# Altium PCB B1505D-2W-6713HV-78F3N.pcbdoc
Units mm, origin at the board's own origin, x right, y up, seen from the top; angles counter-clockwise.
Board outline 50 x 30 mm, 2 copper layers (Top Layer, Bottom Layer), stack 0.78 mm thick; 21 components, 11 nets, 44 pads, 54 vias.
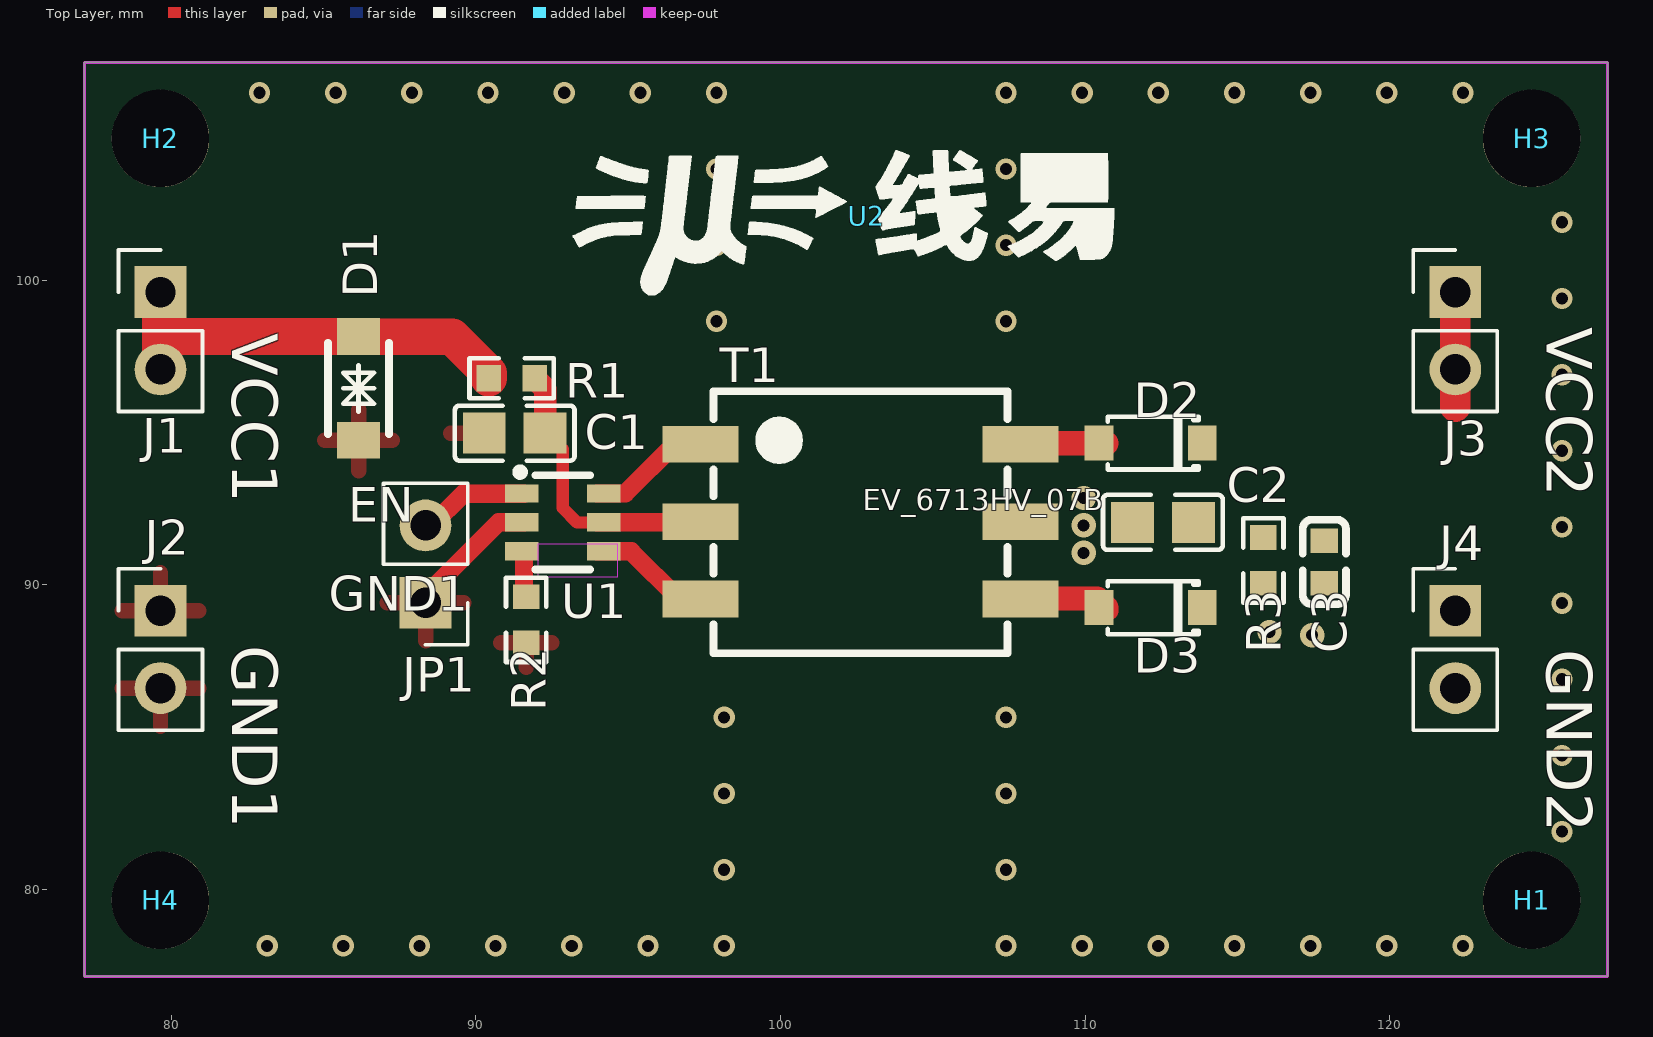
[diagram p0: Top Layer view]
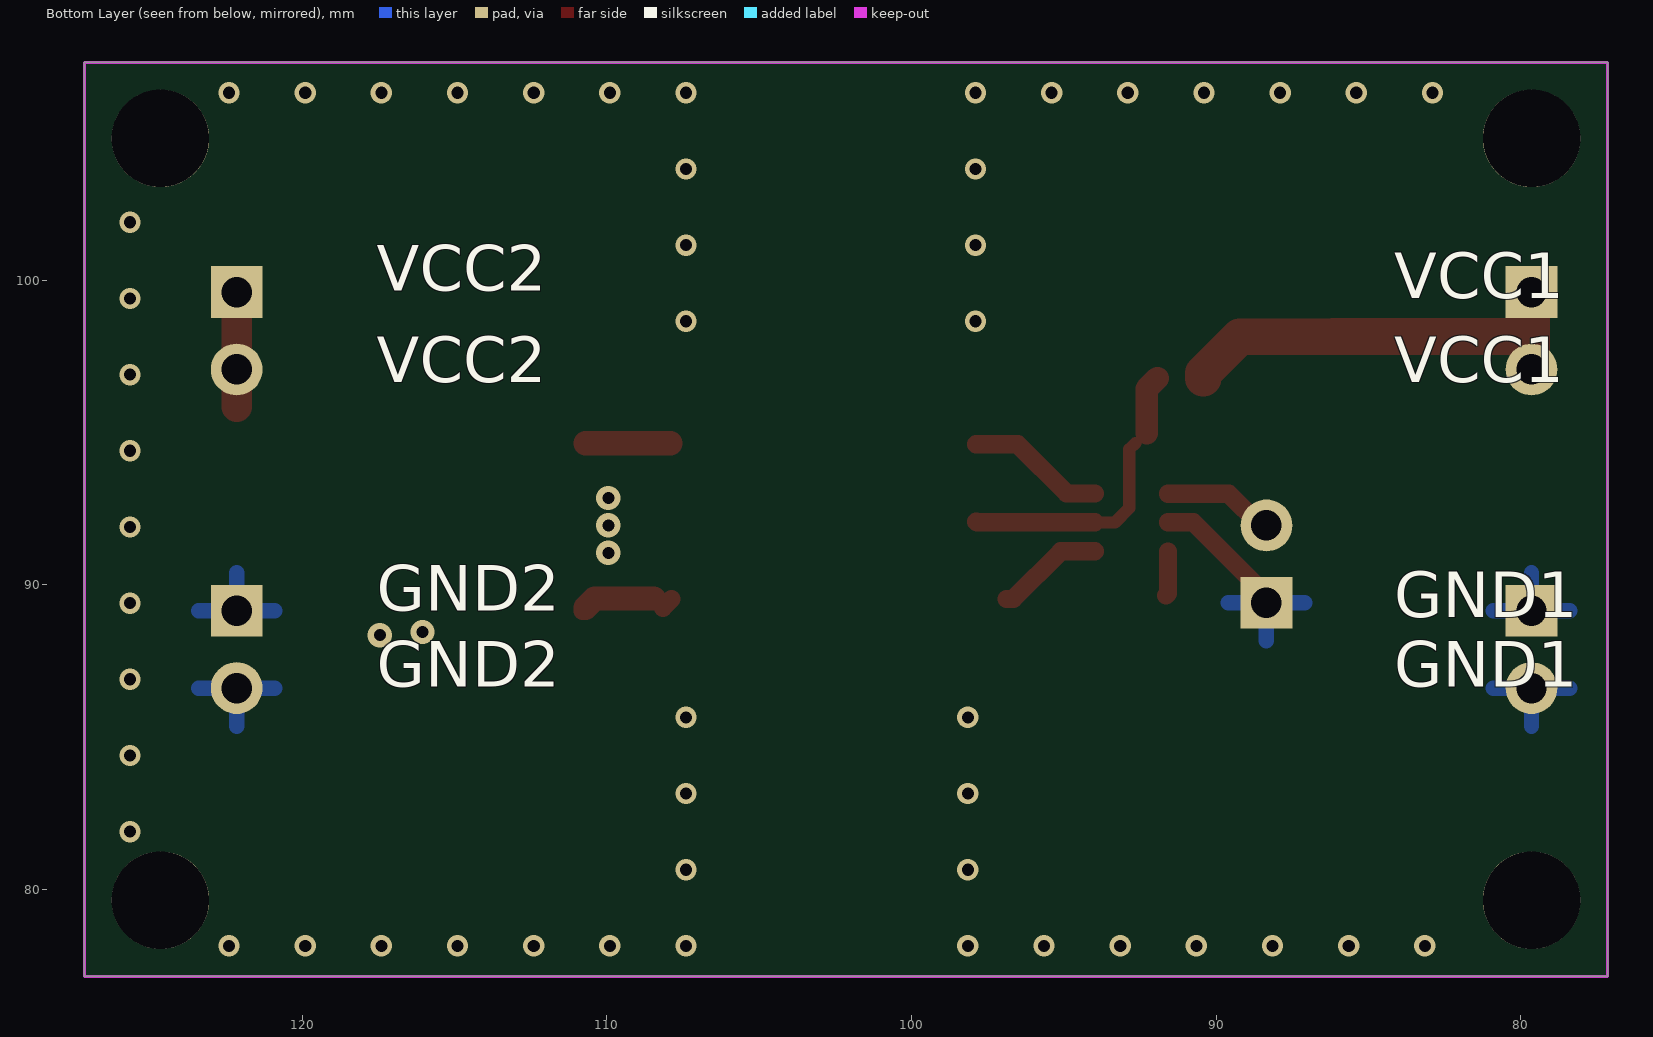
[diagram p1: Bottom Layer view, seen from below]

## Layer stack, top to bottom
Top Solder Mask Layer: solder mask 0.01, Dk 0
Top Layer: signal copper 0.035
Dielectric1: surface 0.71, FR4, Dk 4.5
Bottom Layer: signal copper 0.035
Bottom Solder Mask Layer: solder mask 0.01, Dk 0

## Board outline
77.15,107.15 127.15,107.15 127.15,77.15 77.15,77.15

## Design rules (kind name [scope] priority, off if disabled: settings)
BoardOutlineClearance safeClearance [All] p0: genericclearance=0.254 ignorepadtopadclearanceinfootprint=FALSE except(0: Arc-SplitContinuation Track-SplitContinuation SMDPad-SplitContinuation THPad-SplitContinuation Via-SplitContinuation Fill-SplitContinuation Poly-SplitContinuation Region-SplitContinuation Text-SplitContinuation)
BoardOutlineClearance Plane_innerPlane [All] p0: genericclearance=0.254 ignorepadtopadclearanceinfootprint=FALSE except(0: Arc-SplitContinuation Track-SplitContinuation SMDPad-SplitContinuation THPad-SplitContinuation Via-SplitContinuation Fill-SplitContinuation Poly-SplitContinuation Region-SplitContinuation Text-SplitContinuation)
BoardOutlineClearance Copper_CopperRegion [All] p0: genericclearance=0.254 ignorepadtopadclearanceinfootprint=FALSE except(0: Arc-SplitContinuation Track-SplitContinuation SMDPad-SplitContinuation THPad-SplitContinuation Via-SplitContinuation Fill-SplitContinuation Poly-SplitContinuation Region-SplitContinuation Text-SplitContinuation)
BoardOutlineClearance Copper_CopperRegion1 [All] p0: genericclearance=0.254 ignorepadtopadclearanceinfootprint=FALSE except(0: Arc-SplitContinuation Track-SplitContinuation SMDPad-SplitContinuation THPad-SplitContinuation Via-SplitContinuation Fill-SplitContinuation Poly-SplitContinuation Region-SplitContinuation Text-SplitContinuation)
BoardOutlineClearance Copper_CopperRegion2 [All] p0: genericclearance=0.254 ignorepadtopadclearanceinfootprint=FALSE except(0: Arc-SplitContinuation Track-SplitContinuation SMDPad-SplitContinuation THPad-SplitContinuation Via-SplitContinuation Fill-SplitContinuation Poly-SplitContinuation Region-SplitContinuation Text-SplitContinuation)
BoardOutlineClearance Copper_CopperRegion3 [All] p0: genericclearance=0.254 ignorepadtopadclearanceinfootprint=FALSE except(0: Arc-SplitContinuation Track-SplitContinuation SMDPad-SplitContinuation THPad-SplitContinuation Via-SplitContinuation Fill-SplitContinuation Poly-SplitContinuation Region-SplitContinuation Text-SplitContinuation)
BoardOutlineClearance Copper_CopperRegion4 [All] p0: genericclearance=0.254 ignorepadtopadclearanceinfootprint=FALSE except(0: Arc-SplitContinuation Track-SplitContinuation SMDPad-SplitContinuation THPad-SplitContinuation Via-SplitContinuation Fill-SplitContinuation Poly-SplitContinuation Region-SplitContinuation Text-SplitContinuation)
BoardOutlineClearance otherClearance [All] p0: genericclearance=0.254 ignorepadtopadclearanceinfootprint=FALSE except(0: Arc-SplitContinuation Track-SplitContinuation SMDPad-SplitContinuation THPad-SplitContinuation Via-SplitContinuation Fill-SplitContinuation Poly-SplitContinuation Region-SplitContinuation Text-SplitContinuation)
Clearance safeClearance [All] p1: gap=0.178 ignorepadtopadclearanceinfootprint=FALSE
Clearance Plane_innerPlane [All] p1: gap=0.178 ignorepadtopadclearanceinfootprint=FALSE
Clearance Copper_CopperRegion [All] p1: gap=0.178 ignorepadtopadclearanceinfootprint=FALSE
Clearance Copper_CopperRegion1 [All] p1: gap=0.178 ignorepadtopadclearanceinfootprint=FALSE
Clearance Copper_CopperRegion2 [All] p1: gap=0.178 ignorepadtopadclearanceinfootprint=FALSE
Clearance Copper_CopperRegion3 [All] p1: gap=0.178 ignorepadtopadclearanceinfootprint=FALSE
Clearance Copper_CopperRegion4 [All] p1: gap=0.178 ignorepadtopadclearanceinfootprint=FALSE
Clearance otherClearance [All] p1: gap=0.178 ignorepadtopadclearanceinfootprint=FALSE
DiffPairsRouting differentialPair [All] p1: maxuncoupledlength=10 minlimit=5.9843 maxlimit=Infinity mostfreqgap=5.9843 toplayer_minwidth=5 toplayer_prefwidth=10 toplayer_maxwidth=100 bottomlayer_minwidth=5 bottomlayer_prefwidth=10 bottomlayer_maxwidth=100
PasteMaskExpansion Common [All] p1: expansion=0
PlaneConnect innerPlane [All] p1: planeconnectstyle=Relief reliefexpansion=0.508 reliefentries=4 reliefconductorwidth=0.254 reliefairgap=0.254
PolygonConnect CopperRegion [All] p1: connectstyle=Relief reliefentries=4 reliefconductorwidth=20 polygonreliefangle="90 Angle" airgapwidth=15.748
PolygonConnect CopperRegion1 [All] p1: connectstyle=Direct reliefentries=4 reliefconductorwidth=10 polygonreliefangle="90 Angle" airgapwidth=10
PolygonConnect CopperRegion2 [All] p1: connectstyle=Relief reliefentries=4 reliefconductorwidth=0 polygonreliefangle="90 Angle" airgapwidth=0.9843
PolygonConnect CopperRegion3 [All] p1: connectstyle=Relief reliefentries=4 reliefconductorwidth=0 polygonreliefangle="90 Angle" airgapwidth=0.9843
PolygonConnect CopperRegion4 [All] p1: connectstyle=Relief reliefentries=4 reliefconductorwidth=0 polygonreliefangle="90 Angle" airgapwidth=0.9843
RoutingVias viaSize [All] p1: viastyle="Through Hole" holewidth=12.0078 minholewidth=11.811 maxholewidth=236.1812 width=12.0078 minwidth=11.811 maxwidth=236.1812
SolderMaskExpansion Common [All] p1: useseparateexpansions=TRUE expansion=0 expansionbottom=0
Width trackWidth [All] p1: maxlimit=100 minlimit=5 preferedwidth=10

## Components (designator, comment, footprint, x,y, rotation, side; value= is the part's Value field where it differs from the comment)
C1 "" C0805 91.276,94.98 r0 top
C2 "" C0805 112.55,92.05 r0 top
C3 "" C0603 117.85,90.75 r90 top
D1 "" SOD-123FL_L2.8-W1.8-LS3.7-BI 86.15,96.45 r270 top
D2 "" SOD-123_L2.8-W1.8-LS3.7-RD 112.15,94.65 r180 top
D3 "" SOD-123_L2.8-W1.8-LS3.7-RD 112.15,89.25 r180 top
H1 "" MountingHole:MountingHole_3.2mm_M3 124.65,79.65 r0 top
H2 "" MountingHole:MountingHole_3.2mm_M3 79.65,104.65 r0 top
H3 "Mechanical_MountingHole" MountingHole:MountingHole_3.2mm_M3 124.65,104.65 r0 top
H4 "" MountingHole:MountingHole_3.2mm_M3 79.65,79.65 r0 top
J1 "" Connector_PinHeader_2.54mm:PinHeader_1x02_P2.54mm_Vertical 79.65,99.61 r0 top
J2 "" Connector_PinHeader_2.54mm:PinHeader_1x02_P2.54mm_Vertical 79.65,89.15 r0 top
J3 "" Connector_PinHeader_2.54mm:PinHeader_1x02_P2.54mm_Vertical 122.15,99.61 r0 top
J4 "" Connector_PinHeader_2.54mm:PinHeader_1x02_P2.54mm_Vertical 122.15,89.15 r0 top
JP1 "" Connector_PinHeader_2.54mm:PinHeader_1x02_P2.54mm_Vertical 88.35,89.41 r180 top
R1 "" R0603 91.176,96.78 r0 top
R2 "" R0603 91.65,88.85 r90 top
R3 "" R0603 115.85,90.8 r270 top
T1 "" XFMR-SMD_CMT78GFN1 102.625,92.075 r0 top
U1 "" SOT-23-6_L2.9-W1.6-P0.95-LS2.8-BR 92.85,92.05 r180 top
U2 "" LOGO_19x5mm 102.833,102.108 r0 top

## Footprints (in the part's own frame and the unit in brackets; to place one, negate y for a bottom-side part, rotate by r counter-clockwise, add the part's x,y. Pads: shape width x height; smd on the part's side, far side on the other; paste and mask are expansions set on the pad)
C0603 [mm]
  rect 0.8x0.9 smd: 1(-0.7,0) 2(0.7,0)
  silkscreen extent -1.39,-0.71 1.39,0.71
C0805 [mm]
  rect 1.41x1.35 smd: 1(-1,0) 2(1,0)
  silkscreen extent -1.96,-0.9 1.96,0.9
Connector_PinHeader_2.54mm:PinHeader_1x02_P2.54mm_Vertical [mm]
  rect 1.7x1.7 hole 1: 1(0,0)
  round 1.7 hole 1: 2(0,-2.54)
  silkscreen extent -1.38,-3.92 1.38,1.38
LOGO_19x5mm [mm]
  silkscreen extent -9.65,-2.6 8.13,2.16
MountingHole:MountingHole_3.2mm_M3 [mm]
  round 3.2 hole 3.2 unplated: ""(0,0)
R0603 [mm]
  rect 0.806x0.864 smd: 1(-0.753,0) 2(0.753,0)
  silkscreen extent -1.39,-0.66 1.39,0.66
SOD-123_L2.8-W1.8-LS3.7-RD [mm]
  rect 0.95x1.15 smd: 1(-1.692,0) 2(1.692,0)
  silkscreen extent -1.58,-0.87 1.41,0.87
SOD-123FL_L2.8-W1.8-LS3.7-BI [mm]
  rect 1.2x1.4 smd: 1(-1.7,0) 2(1.7,0)
  silkscreen extent -1.5,-1 1.5,1
SOT-23-6_L2.9-W1.6-P0.95-LS2.8-BR [mm]
  rect 1.1x0.6 smd: 1(1.35,-0.95) 2(1.35,0) 3(1.35,0.95) 4(-1.35,0.95) 5(-1.35,0) 6(-1.35,-0.95)
  silkscreen extent -0.9,-1.78 1.52,1.55
XFMR-SMD_CMT78GFN1 [mm]
  rect 2.5x1.2 smd: 1(-5.25,2.54) 2(-5.25,0) 3(-5.25,-2.54) 4(5.25,-2.54) 5(5.25,0) 6(5.25,2.54)
  silkscreen extent -4.83,-4.32 4.83,4.28

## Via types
v1: diameter 0.7, hole 0.4, Top Layer to Bottom Layer, 49 vias
v2: diameter 0.8, hole 0.4, Top Layer to Bottom Layer, 5 vias

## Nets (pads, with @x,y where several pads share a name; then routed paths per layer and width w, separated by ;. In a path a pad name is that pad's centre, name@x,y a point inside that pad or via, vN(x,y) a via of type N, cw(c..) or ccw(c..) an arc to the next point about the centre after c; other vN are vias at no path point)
$1N1: T1.3 U1.4 | length 3.5
  Top Layer w0.6: U1.4@93.988,91.1 95.1,91.1 96.665,89.535 T1.3@96.875,89.535
$1N9: D3.2 T1.4 | length 2.9
  Top Layer w0.6: T1.4 T1.4@108.16,89.25 ; D3.2@110.7,89.25 D3.2@110.8,89.15
  Top Layer w0.8: T1.4@108.46,89.55 110.4,89.55 D3.2@110.7,89.25
$1N11: C1.2 R1.2 T1.2 U1.5 | length 9.4
  Top Layer w0.4: C1.2@92.65,94.65 92.85,94.45 92.85,92.525 93.325,92.05 U1.5@93.988,92.05
  Top Layer w0.6: U1.5@93.988,92.05 97.85,92.05 T1.2@97.875,92.075
  Top Layer w0.749: R1.2 92.276,96.433 C1.2
$1N21: T1.1 U1.6 | length 4.6
  Top Layer w0.6: U1.6@93.988,93 94.9,93 96.515,94.615 T1.1@97.875,94.615
$1N24: D2.2 T1.6 | length 2.8
  Top Layer w0.6: T1.6 T1.6@107.91,94.65
  Top Layer w0.8: T1.6@107.91,94.65 D2.2@110.7,94.65
CLK: R2.2 U1.3 | length 1.5
  Top Layer w0.6: U1.3@91.58,91.085 91.58,89.72 R2.2@91.65,89.65
EN: JP1.2 U1.1 | length 3.5
  Top Layer w0.6: JP1.2@88.55,91.95 89.59,92.99 U1.1@91.58,92.99
GND1: C1.1 D1.2 J2.1 J2.2 JP1.1 R2.1 U1.2 | length 4.5
  Top Layer w0.6: JP1.1 88.35,89.65 90.75,92.05 U1.2@91.58,92.05
  other v1: 83.15,78.15 85.65,78.15 88.15,78.15 90.65,78.15 93.15,78.15 95.65,78.15 98.15,78.15 98.15,80.65 98.15,83.15 98.15,85.65 97.9,98.65 97.9,101.15 97.9,103.65 82.9,106.15 85.4,106.15 87.9,106.15 90.4,106.15 92.9,106.15 95.4,106.15 97.9,106.15
GND2: C2.1 C3.1 J4.1 J4.2 R3.2 T1.5
  other v1: 107.4,78.15 109.9,78.15 112.4,78.15 114.9,78.15 117.4,78.15 119.9,78.15 122.4,78.15 107.4,80.65 125.65,81.9 107.4,83.15 125.65,84.4 107.4,85.65 125.65,86.9 125.65,89.4 125.65,91.9 125.65,94.4 125.65,96.9 107.4,98.65 125.65,99.4 107.4,101.15 125.65,101.9 107.4,103.65 107.4,106.15 109.9,106.15 112.4,106.15 114.9,106.15 117.4,106.15 119.9,106.15 122.4,106.15
  other v2: 117.45,88.35 116.05,88.45 109.95,91.05 109.95,91.95 109.95,92.85
VCC1: D1.1 J1.1 J1.2 R1.1 | length 14.1
  Top Layer w1.199: D1.1 89.224,98.15 90.423,96.951 R1.1
  Top Layer w1.2: J1.2 J1.2@79.65,97.9 ; J1.1 J1.2@79.65,97.9 ; D1.1 79.9,98.15 J1.2@79.65,97.9
VCC2: C2.2 C3.2 D2.1 D3.1 J3.1 J3.2 R3.1 | length 3.8
  Top Layer w1: 122.15,95.85 J3.2 J3.1
pads on no net: H1. H2. H3. H4.

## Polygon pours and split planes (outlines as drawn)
VCC2 on Top Layer (solid, remove dead copper, pour order 0): 112.75,95.75 114.65,95.75 114.75,95.65 114.75,93.65 119.65,93.65 120.35,94.15 120.35,101.45 123.95,101.45 123.95,93.65 121.35,91.05 114.85,91.05 114.55,90.75 114.55,88.15 112.75,88.15
GND1 on Top Layer (solid, remove dead copper, pour order 2): 98.65,77.15 77.15,77.15 77.15,107.15 98.65,107.15
GND1 on Bottom Layer (solid, remove dead copper, pour order 6): 98.65,77.15 77.15,77.15 77.15,107.15 98.65,107.15
GND2 on Top Layer (solid, remove dead copper, pour order 4): 127.15,77.15 106.65,77.4 106.65,107.4 127.15,107.15
GND2 on Bottom Layer (solid, remove dead copper, pour order 8): 127.15,77.15 106.65,77.15 106.65,107.15 127.15,107.15

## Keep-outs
Top Layer:
  region: 92.05,91.35 94.65,91.35 94.65,90.25 92.05,90.25
Board Outline Layer:
  the board outline again, w0.1

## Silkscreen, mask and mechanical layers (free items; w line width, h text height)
Top Silkscreen Layer:
  text "VCC2" at 125.15,98.45 h1.5 r270
  text "VCC1" at 82.005,98.25 h1.5 r270
  text "EV_6713HV_07B" at 102.706,92.456 h0.7
  text "EN" at 85.815,92.075 h1.14
  text "GND1" at 85.18,89.154 h1.14
  text "GND1" at 82.005,88.011 h1.5 r270
  text "GND2" at 125.15,87.88 h1.5 r270
Bottom Silkscreen Layer:
  text "VCC2" at 117.55,99.65 h1.5
  text "VCC1" at 84.15,99.4 h1.5
  text "VCC1" at 84.15,96.65 h1.5
  text "VCC2" at 117.55,96.65 h1.5
  text "GND2" at 117.55,89.15 h1.5
  text "GND1" at 84.15,88.94 h1.5
  text "GND1" at 84.15,86.65 h1.5
  text "GND2" at 117.55,86.65 h1.5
